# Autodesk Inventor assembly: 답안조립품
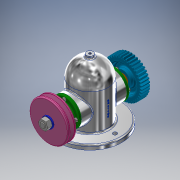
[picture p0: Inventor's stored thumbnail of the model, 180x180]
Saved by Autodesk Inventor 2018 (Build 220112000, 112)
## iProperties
Created: 2019-11
Part Number: 답안조립품
Material: 일반
Document SubType Name: Assembly
Designer: CAD
Author: CAD
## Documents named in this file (14)
- C:\Users\CAD\Desktop\491104V1042\답안조립품.iam
- C:\Users\CAD\Desktop\491104V1042\본체.ipt
- C:\Users\CAD\Desktop\491104V1042\볼트 M4.ipt
- C:\Users\CAD\Desktop\491104V1042\부시.ipt
- C:\Users\CAD\Desktop\491104V1042\스퍼기어.ipt
- C:\Users\CAD\Desktop\491104V1042\오일 실 26 38 8.ipt
- C:\Users\CAD\Desktop\491104V1042\와셔 12x24.ipt
- C:\Users\CAD\Desktop\491104V1042\축.ipt
- C:\Users\CAD\Desktop\491104V1042\커버.ipt
- C:\Users\CAD\Desktop\491104V1042\키 5x5x12.ipt
- C:\Users\CAD\Desktop\491104V1042\V-벨트풀리.ipt
- V-벨트풀리.ipt
- C:\Users\CAD\Desktop\491104V1042\너트 M12x1.25.ipt
- C:\Users\CAD\Desktop\491104V1042\베어링 6203.ipt
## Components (1 placed, 1 different names)
1. V-벨트풀리:1
## Named parameters: d41_d39 = 0, d42_d40 = 0
